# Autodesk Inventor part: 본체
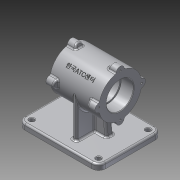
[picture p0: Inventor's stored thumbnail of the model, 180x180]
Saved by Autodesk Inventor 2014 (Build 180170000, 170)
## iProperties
Created: 2015-12
Part Number: 본체
Material: 알루미늄 6061
Document SubType Name: Modeling
Designer: test_03
Density: 2.71 g/cm^3
Appearance: 알루미늄 - 평지
Mass: 1165.38 g
Surface Area: 815.057 cm^2
Volume: 430.029 cm^3
Author: test_03
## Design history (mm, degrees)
sketch "스케치1"
  geometry: L1 (-42.5, 0)-(42.5, 0); L2 (-42.5, 23.5)-(-20.5, 23.5); L3 (-20.5, 23.5)-(-20.5, 21); L4 (-20.5, 21)-(20.5, 21); L5 (20.5, 21)-(20.5, 23.5); L6 (20.5, 23.5)-(42.5, 23.5); L7 (42.5, 23.5)-(42.5, 37); L8 (42.5, 37)-(-42.5, 37); L9 (-42.5, 37)-(-42.5, 23.5); 5 further points
  constraints: 18 end point, 6 parallel, 4 midpoint, 3 vertical alignment, 2 coincident, 1 collinear, 1 horizontal, 1 perpendicular
  dimensions: "d0" = 85 distance of L1.start L1.end; "d1" = 42 diameter of L4 L1; "d2" = 47 diameter of L6 L1; "d3" = 47 diameter of L2 L1; "d4" = 74 diameter of L8 L1; "d5" = 22 distance of L2.start L2.end
revolve "회전1" sketch "스케치1" stored, may be unused: angle "d6" = 90 deg
node "작업 평면1"
sketch "스케치3"
  geometry: L1 (-68, 55)-(48, 55); L2 (60, 43)-(60, -43); L3 (48, -55)-(-68, -55); L4 (-80, -43)-(-80, 43); C1 r 4 at (-68, 43); C2 r 4 at (48, 43); C3 r 4 at (48, -43); C4 r 4 at (-68, -43); A1 r 12 centre (-68, 43) between (-68, 55) and (-80, 43); A2 r 12 centre (-68, -43) between (-80, -43) and (-68, -55); A3 r 12 centre (48, -43) between (48, -55) and (60, -43); A4 r 12 centre (48, 43) between (60, 43) and (48, 55); 5 further points
  constraints: 8 centre point, 8 end point, 8 point on circle, 8 tangent, 6 equal radius, 6 point on line, 4 coincident, 2 parallel, 1 horizontal, 1 horizontal alignment, 1 midpoint, 1 perpendicular
  dimensions: "d11" = 110 distance of point (60, 55) point (60, -55); "d12" = 140 distance of point (-80, 55) point (60, 55); "d13" = 80 distance from line of point (0, 0) L4; "d14" = 12 radius of A1; "d15" = 8 diameter of C1
extrude "돌출2" join sketch "스케치3" distance "d16" = 10; taper "d17" = 0 deg
sketch "스케치4"
  geometry: L1 (43, -70)-(-43, -70) reference; L2 (-37, 0)-(-37, -70); L3 (37, 0)-(37, -70); A1 r 37 centre (0, 0) between (-37, 0) and (37, 0) reference; 1 further point
  constraints: 4 end point, 2 perpendicular, 2 point on circle, 2 point on line, 2 tangent
extrude "돌출3" join sketch "스케치4" stored distance "d18" = 8; taper "d19" = 0 deg
sketch "스케치5"
  geometry: L1 (-42.5, -37)-(42.5, -37) reference; L2 (-48, -70)-(68, -70) reference; L3 (-20.948, -37)-(-25, -70); L4 (20.948, -37)-(25, -70); L5 (0, 0)-(0, -70)
  constraints: 6 end point, 5 point on line, 1 perpendicular, 1 other
  dimensions: "d20" = 97 deg angle of L2 L3; "d21" = 50 distance of L3.end L4.end
feature "리브1" dims "d22" = 1, "d23" = 12, "d24" = 0, "d25" = 0, "d26" = 1, "d27" = 1
feature "리브2" dims "d28" = 1, "d29" = 12, "d30" = 0, "d31" = 0, "d32" = 1, "d33" = 1
sketch "스케치7"
  geometry: L1 (-37, 0)-(0, 0); L2 (0, 0)-(-37.194, 37.194); 1 further point
  constraints: 4 end point, 1 horizontal, 1 horizontal alignment, 1 other
  dimensions: "d34" = 45 deg angle of L1 L2
node "작업 평면2"
sketch "스케치8"
  geometry: 2 further points
  constraints: 1 coincident, 1 other
feature "엠보싱1" sketch "스케치8" dims "d35" = 0.5, "d36" = 0
sketch "스케치9"
  geometry: C1 r 23.5 at (0, 0) reference; C2 r 7 at (-37, 0); C3 r 6.24 at (0, -37); C4 r 8.855 at (0, 37); C5 r 6.29 at (37, 0); A1 r 37 centre (0, 0) between (-37, 0) and (0, -37) reference
  constraints: 4 centre point, 4 point on circle, 1 horizontal alignment
  dimensions: "d37" = 14 diameter of C2
extrude "돌출4" join sketch "스케치9" distance "d38" = 15; taper "d39" = 0 deg
fillet "모깎기1" dims "d40" = 3
fillet "모깎기2" dims "d41" = 3
fillet "모깎기3" dims "d42" = 0.3
chamfer "모따기1" distance "d43" = 1; stored, may be unused: second distance "d44" = 2, angle "d45" = 45 deg
sketch "스케치11"
  geometry: 1 further point
hole "구멍1" diameter "d51" = 3.242; stored, may be unused: countersink angle "d55" = 90 deg, drill point angle "d57" = 118 deg; dims "d49" = 10, "d50" = 10, "d52" = 9, "d53" = 4, "d54" = 2, "d56" = 11
sketch "스케치13"
  geometry: L1 (-27.5, 37)-(42.5, 37) reference; L2 (-42.5, 36.338)-(-42.5, 36.338) reference; L3 (-42.5, 44)-(-27.5, 44) reference; L4 (-27.5, 37)-(-30.048, 44); L5 (-27.5, 44)-(-27.5, 37); L6 (-27.5, 44)-(-30.048, 44); L7 (108, 0)-(-88, 0) reference; L8 (-27.5, 36.338)-(-27.5, 36.338) reference; L9 (-27.5, 36.338)-(-42.5, 36.338) reference; L10 (-42.5, 36.338)-(-27.5, 36.338) reference; 1 further point
  constraints: 6 end point, 1 perpendicular, 1 point on line
  dimensions: "d63" = 110 deg angle of L1 L4
revolve "회전2" sketch "스케치13" stored, may be unused: angle "d64" = 90 deg
sketch "스케치14"
  geometry: L1 (27.5, 44)-(42.5, 44) reference; L2 (-27.5, 37)-(27.5, 37) reference; L3 (27.5, 37)-(30.048, 44); L4 (27.5, 37)-(27.5, 44); L5 (27.5, 44)-(30.048, 44); L6 (108, 0)-(-88, 0) reference; 1 further point
  constraints: 6 end point, 2 perpendicular, 1 point on line
  dimensions: "d65" = 110 deg angle of L2 L3
revolve "회전3" sketch "스케치14" stored, may be unused: angle "d66" = 90 deg
fillet "모깎기11" dims "d72" = 3
fillet "모깎기12" dims "d73" = 3
node "솔리드1"
pattern_circular "원형 패턴1" dims angle "d59" = 360 deg
mirror "대칭1"
node "투영된 루프1"
